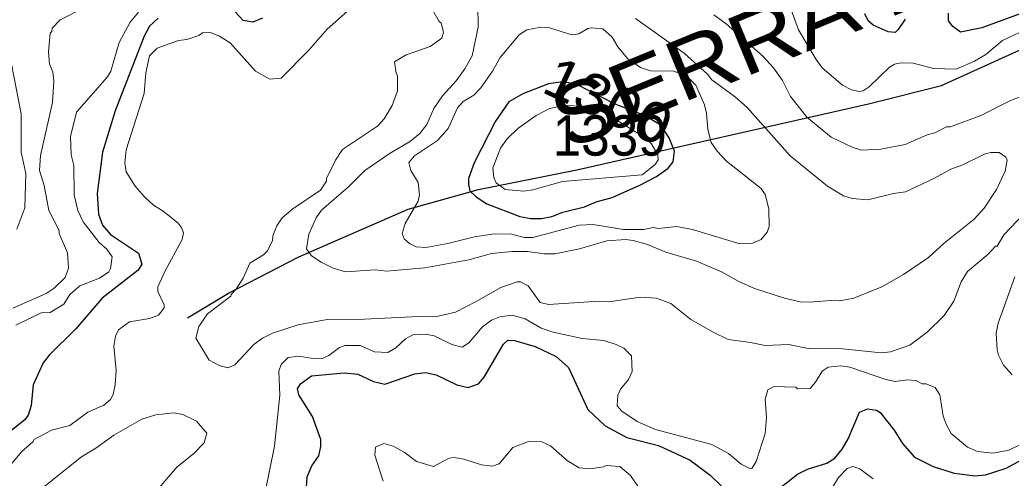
# Model space of a CAD drawing. Extents: x 598.3 to 623.2, y 6902.2 to 6930.1.
# Drawn here: x 612.34 to 614.303, y 6920.79 to 6921.698 of the extents above; entities that cross this region are included whole.
import ezdxf
from ezdxf.enums import TextEntityAlignment as Align

# ---------------------------------------------------------------- set-up
doc = ezdxf.new("R2010")
doc.units = 0
doc.header["$LTSCALE"] = 0.032
for name, color, linetype, lineweight in [('1', 7, 'Continuous', 25), ('2', 7, 'Continuous', 13), ('26', 7, 'Continuous', 25)]:
    doc.layers.add(name, color=color, linetype=linetype, lineweight=lineweight)
doc.layers.add('21', color=7, linetype='Continuous')
doc.layers.add('61', color=7, linetype='Continuous')

msp = doc.modelspace()

# ---------------------------------------------------------------- linework, layer by layer
at = {"layer": '1'}
for points in [[(612.8206, 6921.7014), (612.8014, 6921.6935), (612.7821, 6921.6968), (612.7496, 6921.7323)], [(614.0933, 6921.7), (614.0798, 6921.6792), (614.0735, 6921.6734), (614.0597, 6921.6748), (614.03, 6921.6876), (614.0202, 6921.6967), (614.0134, 6921.7104)], [(614.3265, 6921.7121), (614.2455, 6921.6829), (614.2032, 6921.6743), (614.1878, 6921.6849), (614.1792, 6921.6963), (614.1792, 6921.7116)], [(612.6136, 6921.7016), (612.5967, 6921.6861), (612.5858, 6921.666), (612.5285, 6921.5183), (612.5035, 6921.4361), (612.4931, 6921.3542), (612.4954, 6921.3133), (612.5037, 6921.2918), (612.519, 6921.2729), (612.5747, 6921.2361), (612.5811, 6921.2141), (612.5742, 6921.2025), (612.5027, 6921.147), (612.4507, 6921.0861), (612.3979, 6921.034), (612.3858, 6921.0189), (612.3662, 6920.9753), (612.3618, 6920.9342), (612.3563, 6920.9151), (612.3497, 6920.9059), (612.3235, 6920.8855)], [(612.9075, 6920.7715), (612.909, 6920.793), (612.9182, 6920.8147), (612.9317, 6920.8341), (612.9358, 6920.8529), (612.9358, 6920.8667), (612.9191, 6920.9125), (612.8923, 6920.955), (612.8898, 6920.9673), (612.8959, 6920.9768), (612.9173, 6920.9929), (612.9824, 6920.9989), (613.0089, 6920.9964), (613.0404, 6920.9814), (613.0628, 6920.9764), (613.1222, 6920.9969), (613.143, 6920.9997), (613.1644, 6920.9948), (613.2055, 6920.9749), (613.2275, 6920.97), (613.2482, 6920.9772), (613.2597, 6920.9906), (613.2978, 6921.0558), (613.306, 6921.0637), (613.3193, 6921.0633), (613.3603, 6921.0514), (613.4021, 6921.0313), (613.4263, 6921.0094), (613.4648, 6920.926), (613.499, 6920.8941), (613.5422, 6920.8706), (613.6047, 6920.8547), (613.6673, 6920.8259), (613.7068, 6920.796), (613.7476, 6920.7573)], [(613.9382, 6920.8202), (613.9539, 6920.8296), (613.9689, 6920.8478), (613.9802, 6920.8683), (614.0027, 6920.9209), (614.0194, 6920.9276), (614.0364, 6920.9252), (614.0441, 6920.9203), (614.0717, 6920.8854), (614.0878, 6920.8591), (614.1121, 6920.8319), (614.1487, 6920.8134), (614.1908, 6920.7998), (614.2319, 6920.795), (614.2523, 6920.7966), (614.2934, 6920.81), (614.4182, 6920.8776)], [(613.828, 6920.7573), (613.88, 6920.7983), (613.8998, 6920.8082), (613.9382, 6920.8202)]]:
    msp.add_lwpolyline(points, dxfattribs=at)
msp.add_lwpolyline([(613.4816, 6921.3375), (613.5127, 6921.3464), (613.5676, 6921.371), (613.6011, 6921.3877), (613.6238, 6921.4043), (613.634, 6921.4173), (613.6363, 6921.4379), (613.626, 6921.4647), (613.6091, 6921.49), (613.5754, 6921.5097), (613.5187, 6921.5315), (613.4414, 6921.5707), (613.4147, 6921.5754), (613.387, 6921.5713), (613.336, 6921.5519), (613.3086, 6921.5359), (613.2822, 6921.4976), (613.2399, 6921.4148), (613.2281, 6921.3842), (613.2282, 6921.372), (613.231, 6921.3595), (613.2437, 6921.3475), (613.2647, 6921.3339), (613.3301, 6921.3084), (613.3516, 6921.305), (613.3732, 6921.305), (613.3933, 6921.3088), (613.4153, 6921.3171), (613.4579, 6921.3279)], close=True, dxfattribs=at)
at = {"layer": '2'}
for points in [[(614.3449, 6921.6854), (614.2865, 6921.6573), (614.2532, 6921.63), (614.2308, 6921.6164), (614.1943, 6921.6005), (614.1495, 6921.6021), (614.1093, 6921.6126), (614.0853, 6921.6133), (614.0722, 6921.6103), (614.0626, 6921.6044), (614.0222, 6921.5657), (614.0105, 6921.5575), (614.0025, 6921.5567), (613.9874, 6921.5597), (613.9691, 6921.5688), (613.9292, 6921.6034), (613.9171, 6921.6196), (613.8822, 6921.6787), (613.8651, 6921.7258), (613.8684, 6921.7504), (613.8749, 6921.7666), (613.878, 6921.7823), (613.8773, 6921.7985)], [(613.7128, 6921.0792), (613.6685, 6921.1048), (613.6295, 6921.1365), (613.6009, 6921.147), (613.5683, 6921.1487), (613.5067, 6921.1398), (613.4874, 6921.1406), (613.387, 6921.1342), (613.3701, 6921.1385), (613.3464, 6921.1712), (613.3317, 6921.1791), (613.3247, 6921.1795), (613.2922, 6921.1683), (613.2435, 6921.14), (613.2024, 6921.1193), (613.1651, 6921.1103), (613.1432, 6921.1115), (613.0224, 6921.105), (612.9485, 6921.1049), (612.8912, 6921.0942), (612.8403, 6921.0774), (612.8206, 6921.0676), (612.8038, 6921.0555), (612.7656, 6921.015), (612.7515, 6921.0087), (612.7342, 6921.0131), (612.7145, 6921.0243), (612.6882, 6921.0673), (612.6943, 6921.0907), (612.7115, 6921.1155), (612.7573, 6921.1509), (612.758, 6921.1544), (612.7682, 6921.1648), (612.7819, 6921.1865), (612.7952, 6921.216), (612.8221, 6921.2325), (612.8304, 6921.2408), (612.8402, 6921.2612), (612.8411, 6921.2707), (612.849, 6921.2901), (612.8596, 6921.3063), (612.8801, 6921.3237), (612.9349, 6921.3607), (612.947, 6921.3788), (612.9472, 6921.3842), (612.9652, 6921.4205), (612.9786, 6921.4417), (613.0479, 6921.4877), (613.0611, 6921.5022), (613.0769, 6921.5289), (613.0879, 6921.5575), (613.0879, 6921.588), (613.0849, 6921.5927), (613.0818, 6921.615), (613.1051, 6921.6291), (613.1522, 6921.6455), (613.1758, 6921.6618), (613.1787, 6921.6739), (613.174, 6921.692), (613.1702, 6921.6949), (613.1476, 6921.7344)], [(613.2466, 6921.7291), (613.2475, 6921.6841), (613.2354, 6921.6274), (613.2209, 6921.6014), (613.2041, 6921.5774), (613.1769, 6921.5475), (613.16, 6921.5225), (613.1461, 6921.4909), (613.1323, 6921.4731), (613.1138, 6921.4583), (613.0732, 6921.4343), (613.0229, 6921.4), (612.9905, 6921.3677), (612.9369, 6921.3213), (612.9267, 6921.306), (612.9119, 6921.2734), (612.9075, 6921.2445), (612.9177, 6921.2307), (612.9367, 6921.2179), (612.9604, 6921.2066), (612.9846, 6921.1992), (613.0437, 6921.203), (613.0662, 6921.2006), (613.142, 6921.207), (613.2291, 6921.2228)], [(612.3319, 6921.0933), (612.3816, 6921.1177), (612.3997, 6921.1187), (612.4271, 6921.1347), (612.4388, 6921.1542), (612.4583, 6921.1713), (612.4976, 6921.1862), (612.516, 6921.1992), (612.5195, 6921.2056), (612.5228, 6921.2287), (612.512, 6921.2439), (612.4968, 6921.2573), (612.465, 6921.2979), (612.4546, 6921.3205), (612.447, 6921.3518), (612.4468, 6921.4098), (612.4411, 6921.4306), (612.4401, 6921.4675), (612.4518, 6921.5154), (612.5134, 6921.5853), (612.5199, 6921.5968), (612.5362, 6921.6536), (612.5585, 6921.6935), (612.5747, 6921.7138)], [(612.4691, 6921.7237), (612.4195, 6921.6984), (612.4036, 6921.6818), (612.403, 6921.6755), (612.4, 6921.6723), (612.3967, 6921.6343), (612.3984, 6921.6109), (612.4048, 6921.5945), (612.4072, 6921.5775), (612.4041, 6921.5347), (612.3805, 6921.4296), (612.3789, 6921.3999), (612.3876, 6921.3703), (612.3968, 6921.3206), (612.4177, 6921.2811), (612.4178, 6921.2751)], [(612.9888, 6921.7157), (612.9487, 6921.6797), (612.9117, 6921.6378), (612.8571, 6921.5825), (612.8349, 6921.5809), (612.8064, 6921.5965), (612.756, 6921.653), (612.7353, 6921.6658), (612.7175, 6921.6731), (612.7013, 6921.6724), (612.694, 6921.6675), (612.6706, 6921.6595), (612.6536, 6921.6577), (612.6118, 6921.6422), (612.5965, 6921.6269), (612.5894, 6921.5937), (612.5861, 6921.5524), (612.55, 6921.4407)], [(613.7143, 6921.7082), (613.7386, 6921.6904), (613.8113, 6921.6267), (613.8327, 6921.6036), (613.8505, 6921.5785), (613.8661, 6921.5466), (613.8992, 6921.5048), (613.9471, 6921.4659), (613.9884, 6921.4464), (614.0071, 6921.4403), (614.0454, 6921.4418), (614.0932, 6921.4513), (614.1371, 6921.4707), (614.1519, 6921.4743), (614.1753, 6921.4862), (614.1829, 6921.4864), (614.2436, 6921.5089), (614.3022, 6921.5388), (614.3319, 6921.5496)], [(613.9917, 6921.1471), (614.0475, 6921.1695), (614.0899, 6921.1939), (614.1399, 6921.2277), (614.1707, 6921.2559), (614.2304, 6921.3035), (614.2496, 6921.3254), (614.2745, 6921.3622), (614.2917, 6921.3988), (614.2956, 6921.4201), (614.2925, 6921.4263), (614.2795, 6921.4352), (614.2632, 6921.4352), (614.252, 6921.4326), (614.2078, 6921.4111), (614.184, 6921.4028), (614.1505, 6921.3837), (614.0941, 6921.3573), (614.0705, 6921.3543), (614.0194, 6921.3414), (613.9884, 6921.3445), (613.9711, 6921.3498), (613.9393, 6921.369), (613.8653, 6921.4286), (613.7807, 6921.5245), (613.7572, 6921.5455), (613.7101, 6921.5798), (613.7017, 6921.5905), (613.6558, 6921.6323), (613.5589, 6921.7009)], [(612.3334, 6921.2837), (612.3497, 6921.3261), (612.3513, 6921.394), (612.3425, 6921.4359), (612.3424, 6921.5124), (612.3085, 6921.6851)], [(612.55, 6921.4407), (612.5473, 6921.4141), (612.5504, 6921.3975), (612.568, 6921.369), (612.5863, 6921.3477), (612.6046, 6921.331), (612.6233, 6921.3194), (612.6523, 6921.2962), (612.6603, 6921.2858), (612.6637, 6921.2761), (612.6614, 6921.263), (612.6272, 6921.2011), (612.6129, 6921.1692), (612.613, 6921.1601), (612.6255, 6921.1339), (612.6257, 6921.1279), (612.6142, 6921.1132), (612.5965, 6921.1064), (612.557, 6921.1001), (612.5352, 6921.0839), (612.5291, 6921.0714), (612.5255, 6921.0516), (612.5302, 6921.0044), (612.5287, 6920.9749), (612.5247, 6920.9558), (612.5191, 6920.9458), (612.5063, 6920.9347), (612.4742, 6920.9211), (612.4389, 6920.8947), (612.4025, 6920.8852), (612.3677, 6920.867), (612.3651, 6920.8622), (612.3434, 6920.8428), (612.3091, 6920.802)], [(614.3416, 6921.3279), (614.2891, 6921.2723), (614.2757, 6921.2502), (614.2721, 6921.2496), (614.2577, 6921.2338), (614.2166, 6921.1999), (614.2045, 6921.1792), (614.1896, 6921.1412), (614.1704, 6921.1126), (614.1367, 6921.0794), (614.1029, 6921.0538), (614.0645, 6921.0403), (614.0458, 6921.0387), (613.969, 6921.0467), (613.9014, 6921.0468), (613.8624, 6921.0548), (613.816, 6921.0532), (613.7869, 6921.0589), (613.7429, 6921.0649), (613.7128, 6921.0792)], [(612.4178, 6921.2751), (612.4339, 6921.2369), (612.4363, 6921.2064), (612.4292, 6921.1875), (612.4075, 6921.1667), (612.3916, 6921.1558), (612.3258, 6921.1269)], [(613.2291, 6921.2228), (613.274, 6921.2353), (613.3144, 6921.2393), (613.345, 6921.2394), (613.3785, 6921.2346), (613.3992, 6921.2349), (613.4481, 6921.2448), (613.5022, 6921.2604), (613.5403, 6921.2628), (613.5545, 6921.2612), (613.5829, 6921.2533), (613.6191, 6921.2379), (613.6803, 6921.22), (613.731, 6921.1987), (613.7626, 6921.1805), (613.7947, 6921.166), (613.8547, 6921.1468), (613.8856, 6921.1399), (613.9032, 6921.139), (613.9555, 6921.143), (613.9641, 6921.1415), (613.9917, 6921.1471)], [(614.3055, 6920.9951), (614.2883, 6921.0142), (614.2782, 6921.034), (614.2755, 6921.0443), (614.2739, 6921.0772), (614.2776, 6921.0973), (614.3107, 6921.1892)], [(612.8257, 6920.7627), (612.8444, 6920.8535), (612.8548, 6920.9547), (612.8525, 6921.0021), (612.8575, 6921.0155), (612.8712, 6921.0296), (612.8914, 6921.0322), (612.9207, 6921.0273), (612.9403, 6921.0281), (612.9514, 6921.0334), (612.973, 6921.0494), (612.9844, 6921.0532), (613.0137, 6921.0531), (613.0419, 6921.0408), (613.0683, 6921.0395), (613.0842, 6921.0485), (613.1038, 6921.0661), (613.1182, 6921.074), (613.1433, 6921.0758), (613.1603, 6921.0719), (613.1956, 6921.0552), (613.2159, 6921.05), (613.2288, 6921.0582), (613.2561, 6921.0902), (613.2742, 6921.1033), (613.2906, 6921.1099), (613.3146, 6921.113), (613.3408, 6921.1056), (613.3721, 6921.0875), (613.3958, 6921.0794), (613.4534, 6921.067), (613.4966, 6921.0627), (613.5211, 6921.0553), (613.5362, 6921.0477), (613.5511, 6921.0324), (613.5527, 6921.0018), (613.5452, 6920.9858), (613.5298, 6920.9663), (613.5245, 6920.9546), (613.5227, 6920.9336), (613.5322, 6920.9229), (613.5622, 6920.9023)], [(613.5622, 6920.9023), (613.5991, 6920.8866), (613.7103, 6920.857), (613.7435, 6920.8388), (613.7688, 6920.8178), (613.7869, 6920.8087), (613.7894, 6920.8093), (613.7983, 6920.8234), (613.8164, 6920.8786), (613.819, 6920.9104), (613.8158, 6920.9464), (613.8214, 6920.9649), (613.8331, 6920.9715), (613.8766, 6920.9707), (613.8799, 6920.9674), (613.9049, 6920.968), (613.9161, 6920.9804), (613.929, 6921.0019), (613.9412, 6921.0102), (613.9658, 6921.0127), (613.9839, 6921.0101), (614.055, 6920.9859), (614.0734, 6920.982), (614.0977, 6920.9851), (614.1147, 6920.9835), (614.1274, 6920.9771), (614.1344, 6920.9769), (614.153, 6920.9698), (614.162, 6920.9555), (614.169, 6920.9133), (614.1743, 6920.8969), (614.1843, 6920.8784), (614.2172, 6920.8516), (614.237, 6920.8428), (614.2675, 6920.8395), (614.299, 6920.8457), (614.3245, 6920.858)], [(612.6111, 6920.7656), (612.6503, 6920.8122), (612.6844, 6920.8388), (612.7049, 6920.8604), (612.7098, 6920.8791), (612.6894, 6920.903), (612.6623, 6920.9165), (612.645, 6920.9196), (612.6091, 6920.9156), (612.5811, 6920.9073), (612.526, 6920.8757), (612.4904, 6920.8498), (612.4617, 6920.8323), (612.3799, 6920.7668)], [(613.6014, 6920.7194), (613.5493, 6920.7957), (613.5283, 6920.8131), (613.5008, 6920.8152), (613.4958, 6920.8125), (613.469, 6920.8088), (613.4478, 6920.8105), (613.4242, 6920.8244), (613.3907, 6920.854), (613.3734, 6920.8621), (613.3473, 6920.863), (613.316, 6920.851), (613.2891, 6920.8188), (613.2761, 6920.8137), (613.2541, 6920.8166), (613.2194, 6920.8281), (613.2, 6920.8313), (613.1903, 6920.8298), (613.1588, 6920.8136), (613.1255, 6920.8231), (613.1012, 6920.8414), (613.0789, 6920.8538), (613.061, 6920.859), (613.0441, 6920.8519), (613.0427, 6920.8355), (613.0596, 6920.7841)], [(614.03, 6920.7887), (614.0036, 6920.8087), (613.9895, 6920.8134), (613.9782, 6920.8093), (613.9613, 6920.7918), (613.9195, 6920.7227)]]:
    msp.add_lwpolyline(points, dxfattribs=at)
for points in [[(613.8238, 6921.289), (613.8231, 6921.3238), (613.8163, 6921.352), (613.8079, 6921.3645), (613.7396, 6921.4183), (613.7212, 6921.4383), (613.7093, 6921.4552), (613.7024, 6921.4809), (613.7, 6921.5133), (613.6958, 6921.5303), (613.6789, 6921.5688), (613.6591, 6921.5891), (613.6342, 6921.597), (613.5891, 6921.5972), (613.5693, 6921.6042), (613.5436, 6921.6216), (613.524, 6921.6449), (613.5133, 6921.6639), (613.4942, 6921.6805), (613.4715, 6921.6829), (613.4646, 6921.6813), (613.4472, 6921.6708), (613.4331, 6921.6684), (613.3891, 6921.6829), (613.372, 6921.6838), (613.3438, 6921.6789), (613.3288, 6921.6688), (613.291, 6921.624), (613.2757, 6921.5964), (613.2528, 6921.5637), (613.2391, 6921.5493), (613.2178, 6921.5364), (613.2066, 6921.524), (613.1883, 6921.4831), (613.1669, 6921.4592), (613.1211, 6921.4286), (613.11, 6921.4157), (613.1141, 6921.3999), (613.1285, 6921.3759), (613.1316, 6921.3519), (613.1285, 6921.3394), (613.1031, 6921.2947), (613.097, 6921.2751), (613.101, 6921.2645), (613.1112, 6921.2552), (613.1246, 6921.2488), (613.1436, 6921.2475), (613.1876, 6921.2549), (613.2402, 6921.2685), (613.2801, 6921.2741), (613.3144, 6921.2734), (613.3387, 6921.2669), (613.3557, 6921.2669), (613.4473, 6921.2913), (613.4752, 6921.2927), (613.5355, 6921.283), (613.5756, 6921.2831), (613.5945, 6921.2871), (613.605, 6921.2847), (613.6406, 6921.2887), (613.6722, 6921.2831), (613.7661, 6921.2548), (613.7909, 6921.2556), (613.8083, 6921.2629), (613.8203, 6921.2778)], [(613.2833, 6921.3752), (613.2783, 6921.3857), (613.2767, 6921.405), (613.2918, 6921.4439), (613.305, 6921.4628), (613.3263, 6921.4834), (613.3627, 6921.5091), (613.3891, 6921.5226), (613.4207, 6921.5293), (613.4313, 6921.5286), (613.4775, 6921.5227), (613.4936, 6921.5172), (613.5826, 6921.4617), (613.5901, 6921.4535), (613.6036, 6921.4311), (613.6041, 6921.4213), (613.5983, 6921.4117), (613.5727, 6921.3913), (613.4147, 6921.3778), (613.3558, 6921.3613), (613.3383, 6921.3592), (613.3009, 6921.3621)]]:
    msp.add_lwpolyline(points, close=True, dxfattribs=at)
at = {"layer": '26'}
msp.add_lwpolyline([(612.6719, 6921.1078), (612.7532, 6921.1566), (612.8922, 6921.2289), (613.1091, 6921.3234), (613.2481, 6921.3623), (613.4427, 6921.4012), (614.0207, 6921.532), (614.1655, 6921.5681), (614.519, 6921.7285), (614.9156, 6921.9285), (615.1889, 6922.0964), (615.5389, 6922.3409), (615.9893, 6922.783)], dxfattribs=at)

# ---------------------------------------------------------------- texts
at = {"layer": '21', "width": 0.95}
msp.add_text('1339', height=0.08, dxfattribs=at).set_placement((613.395, 6921.4293))
at = {"layer": '26', "width": 1.15}
msp.add_text('SERRA DOS MACEDOS', height=0.12, rotation=22.374, dxfattribs=at).set_placement((614.3815, 6921.8337), align=Align.CENTER)
at = {"layer": '61', "width": 1.1}
msp.add_text('1300', height=0.08, rotation=334.988, dxfattribs=at).set_placement((613.4886, 6921.5013), align=Align.CENTER)

doc.saveas('drawing.dxf')
